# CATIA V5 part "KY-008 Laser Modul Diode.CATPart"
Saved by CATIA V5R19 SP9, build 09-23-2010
Part number: KY-008 Laser Modul Diode
Bounding box of the stored display mesh (mm): x 0 to 14, y -3.485 to 3.485, z -3.5 to 3.5
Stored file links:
  D:\Temporäre Sachen\Lasermodul KY-008 with mounting for adjustment\KY-008 Laser Modul Diode.CATPart
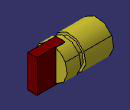
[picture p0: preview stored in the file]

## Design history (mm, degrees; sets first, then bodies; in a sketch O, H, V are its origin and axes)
Body1 (main body)
  Sketch1 on xy-plane, origin (0, 0, 0), H (1, 0, 0), V (0, 1, 0)
    axis line L1 (0, 0) -> (203.5096, 0)
    line L2 (0, 1.5) -> (0, 3.5)
    line L3 (0, 3.5) -> (6, 3.5)
    line L4 (6, 3.5) -> (6, 3)
    line L5 (6, 3) -> (7, 3)
    line L6 (7, 3) -> (7, 3.5)
    point P6 (7, 3.5)
    line L7 (7, 3.5) -> (10, 3.5)
    line L8 (10, 3.5) -> (10, 0)
    point P8 (10, 0)
    line L9 (0, 1.5) -> (3, 1.5)
    line L10 (3, 1.5) -> (3, 0)
    point P10 (3, 0)
    distance L1 L3 = 3.5
    distance L1 L9 = 1.5
    distance L3 L5 = 0.5
    distance L2 L10 = 3
    distance L2 L4 = 6
    distance L4 L6 = 1
    distance L2 L8 = 10
    horizontal: L1 H, L3 H, L5 H, L7 H, L9 H
    vertical: L2 V, L4 V, L6 V, L8 V, L10 V
    coincidence: P6 L3, P8 L1, P10 L1, O L2
  Shaft1: profile Sketch1, axis Sketch1.L1, angle 360
  Sketch2 on xy-plane, origin (0, 0, 0), H (1, 0, 0), V (0, 1, 0)
    point P1 (11, 0)
    line L1 (14, 1) -> (14, -1)
    line L2 (14, -1) -> (8, -1)
    line L3 (8, -1) -> (8, 1)
    line L4 (8, 1) -> (14, 1)
    distance L2 L4 = 2
    distance L1 L3 = 6
    distance L3 V = 8
    coincidence: P1 H
    vertical: L1 V, L3 V
    horizontal: L2 H, L4 H
    equidistance: L1 L3 P1, L2 L4 P1
  Pad1: profile Sketch2, direction (0, 0, 1), length 3.5, mirrored extent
